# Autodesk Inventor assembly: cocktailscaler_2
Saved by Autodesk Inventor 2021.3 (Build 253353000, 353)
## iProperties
Created: 2023-07
Part Number: cocktailscaler_2
Document SubType Name: Assembly
Designer: AdminForWorker
Title: cocktailscaler_2 v34
Author: AdminForWorker
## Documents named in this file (7)
- c:\worker\convert-fusion-r03-cosv3\tmp\job-1\451\output\files\e2bc462c-9dd2-4de9-b2d0-73f4e7c4ef0a\6d4a4bf4-e625-4eb0-8985-9e881d40b9b0.iam
- c:\worker\convert-fusion-r03-cosv3\tmp\job-1\451\output\files\e2bc462c-9dd2-4de9-b2d0-73f4e7c4ef0a\wiegezelle v4.ipt
- c:\worker\convert-fusion-r03-cosv3\tmp\job-1\451\output\files\e2bc462c-9dd2-4de9-b2d0-73f4e7c4ef0a\LCD_TFT_1.8_SPI_ST7735 v1.ipt
- c:\worker\convert-fusion-r03-cosv3\tmp\job-1\451\output\files\e2bc462c-9dd2-4de9-b2d0-73f4e7c4ef0a\touch button TTP223 v1.ipt
- c:\worker\convert-fusion-r03-cosv3\tmp\job-1\451\output\files\e2bc462c-9dd2-4de9-b2d0-73f4e7c4ef0a\bottom.ipt
- c:\worker\convert-fusion-r03-cosv3\tmp\job-1\451\output\files\e2bc462c-9dd2-4de9-b2d0-73f4e7c4ef0a\cellplate.ipt
- c:\worker\convert-fusion-r03-cosv3\tmp\job-1\451\output\files\e2bc462c-9dd2-4de9-b2d0-73f4e7c4ef0a\case_ring.ipt
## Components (7 placed, 6 different names)
1. wiegezelle v4:1
2. LCD_TFT_1.8_SPI_ST7735 v1:1
3. touch button TTP223 v1:1
4. touch button TTP223 v1:2
5. bottom:1
6. cellplate:1
7. case_ring:1
